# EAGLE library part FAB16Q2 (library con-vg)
CONNECTOR female, 16 pins type Q/2, rows AB, grid 2.54 mm / 5.08 mm
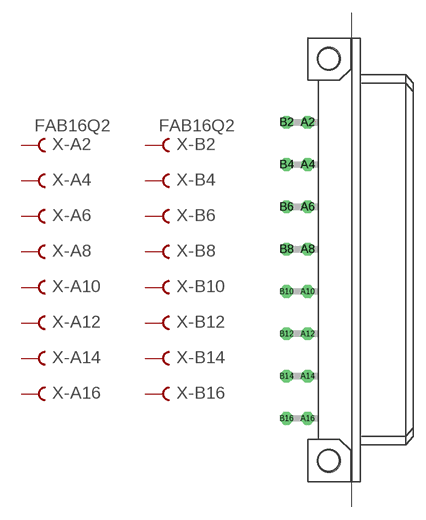
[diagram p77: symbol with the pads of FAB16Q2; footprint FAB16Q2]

Designator prefix X; gates -A4=FEM -A6=FEM -A8=FEM -A10=FEM -A12=FEM -A14=FEM -A16=FEM -B4=FEM -B6=FEM -B8=FEM -B10=FEM -B12=FEM -B14=FEM -B16=FEM -A2=FVAL -B2=FVAL

## FAB16Q2  [FAB16Q2]
A2  -A2:B  pas
A4  -A4:B  pas
A6  -A6:B  pas
A8  -A8:B  pas
A10  -A10:B  pas
A12  -A12:B  pas
A14  -A14:B  pas
A16  -A16:B  pas
B2  -B2:B  pas
B4  -B4:B  pas
B6  -B6:B  pas
B8  -B8:B  pas
B10  -B10:B  pas
B12  -B12:B  pas
B14  -B14:B  pas
B16  -B16:B  pas

## Footprint FAB16Q2 (pad centres in mm)
CONNECTOR female, 16 pins type Q/2, rows AB, grid 2.54 mm / 5.08 mm
drill 1.016 octagon: A2 -2.54,16.51; A4 -2.54,11.43; A6 -2.54,6.35; A8 -2.54,1.27; A10 -2.54,-3.81; A12 -2.54,-8.89; A14 -2.54,-13.97; A16 -2.54,-19.05; B2 -5.08,16.51; B4 -5.08,11.43; B6 -5.08,6.35; B8 -5.08,1.27; B10 -5.08,-3.81; B12 -5.08,-8.89; B14 -5.08,-13.97; B16 -5.08,-19.05
hole 2.794 at 0,-24.136
hole 2.794 at 0,24.136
